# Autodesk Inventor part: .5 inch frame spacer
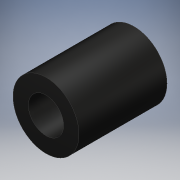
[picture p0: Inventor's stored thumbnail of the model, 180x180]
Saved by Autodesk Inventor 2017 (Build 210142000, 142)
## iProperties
Created: 2016-06
Part Number: .5 inch frame spacer
Material: Generic
Document SubType Name: Modeling
Designer: Stan
Density: 1 g/cm^3
Appearance: Glossy - Black
Author: Stan
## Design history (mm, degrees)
sketch "Sketch1"
  geometry: C1 r 2.54 at (0, 0); C2 r 4.762 at (0, 0); 1 further point
  constraints: 2 centre point, 2 coincident
  dimensions: "d0" = 5.08 diameter of C1; "d1" = 9.525 diameter of C2
extrude "Extrusion1" new body sketch "Sketch1" distance "d2" = 12.7; taper "d3" = 0 deg
body "Solid1"
